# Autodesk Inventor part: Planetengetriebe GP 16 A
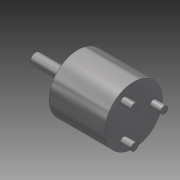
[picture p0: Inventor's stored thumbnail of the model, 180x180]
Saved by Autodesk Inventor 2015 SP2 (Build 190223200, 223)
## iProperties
Created: 2012-07
Part Number: Planetengetriebe GP 16 A
Material: Edelstahl
Document SubType Name: Modeling
Designer: rYan
Mass: 26.4198 g
Surface Area: 14.0202 cm^2
Volume: 3.26978 cm^3
Density: 8.08 g/cm^3
Appearance: Halbpoliert
Author: rYan
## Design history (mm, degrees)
sketch "Skizze1"
  geometry: L1 (-13.625, 0)-(-13.625, 1.5); L2 (-13.625, 1.5)-(-4.475, 1.5); L3 (-4.475, 1.5)-(-4.475, 3); L4 (-4.475, 3)-(-1.875, 3); L5 (-1.875, 3)-(-1.875, 8); L6 (-1.875, 8)-(13.625, 8); L7 (13.625, 8)-(13.625, 0); L8 (13.625, 0)-(-13.625, 0); L9 (0, 9.6)-(0, -1.6) reference; L10 (-19.075, 0)-(19.075, 0) reference; 1 further point
  constraints: 16 end point, 6 parallel, 1 collinear, 1 perpendicular, 1 vertical, 1 other
  dimensions: "d0" = 3 diameter of L2 L8; "d2" = 6 diameter of L4 L8; "d3" = 16 diameter of L6 L8; "d4" = 15.5 distance of L5.end L6.end; "d5" = 2.6 distance of L3.end L4.end; "d6" = 11.75 distance between parallel lines of L5 L1
revolve "Umdrehung1" sketch "Skizze1" stored, may be unused: angle "d7" = 90 deg
sketch "Skizze2" dims "d8" = 10
  geometry: L1 (0, 11.2)-(0, -11.2) reference; C1 r 8 at (0, 0) reference; 3 further points
  constraints: 1 coincident, 1 point on line, 1 vertical alignment, 2 other
hole "Bohrung1" sketch "Skizze2" at (0, 5) diameter "d10" = 1.567; stored, may be unused: countersink angle "d14" = 90 deg, drill point angle "d16" = 0 deg; dims "d11" = 6, "d12" = 4, "d13" = 2, "d15" = 3
pattern_circular "Runde Anordnung1" dims angle "d18" = 360 deg
sketch "Skizze3"
  geometry: L1 (-11.2, 0)-(11.2, 0) reference; L2 (-4.664, -1.5)-(5.169, -1.5); L3 (-2, 1.5)-(2, 1.5); L4 (2, 1.5)-(2, 1.3); L5 (2, 1.3)-(-2, 1.3); L6 (-2, 1.3)-(-2, 1.5); L7 (0, 11.2)-(0, -11.2) reference; C1 r 1.5 at (0, 0) reference; 1 further point
  constraints: 10 end point, 3 parallel, 2 tangent, 1 horizontal, 1 perpendicular, 1 other
  dimensions: "d22" = 2.8 distance between parallel lines of L5 L2; "d24" = 4 distance of L3.start L3.end
extrude "Extrusion1" cut sketch "Skizze3" distance "d25" = 7.8; taper "d26" = 0 deg
sketch "Skizze4" dims "d27" = 11
  geometry: L1 (0, -11.2)-(0, 11.2) reference; C1 r 1 at (0, 5.5); 2 further points
  constraints: 1 centre point, 1 coincident, 1 point on line, 1 vertical alignment, 2 other
  dimensions: "d29" = 2 diameter of C1
extrude "Extrusion2" join sketch "Skizze4" distance "d30" = 3; taper "d31" = 0 deg
pattern_circular "Runde Anordnung2" dims angle "d33" = 360 deg
node "Volumenkörper1"
